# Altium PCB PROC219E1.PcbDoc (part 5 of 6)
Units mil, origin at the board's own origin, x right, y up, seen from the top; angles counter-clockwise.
Board outline 5354.33 x 5354.33 mil, 4 copper layers (Top Layer, Inner Layer 1, Inner Layer 2, Bottom Layer), stack 62.449 mil thick; 579 components, 299 nets, 1709 pads, 802 vias.
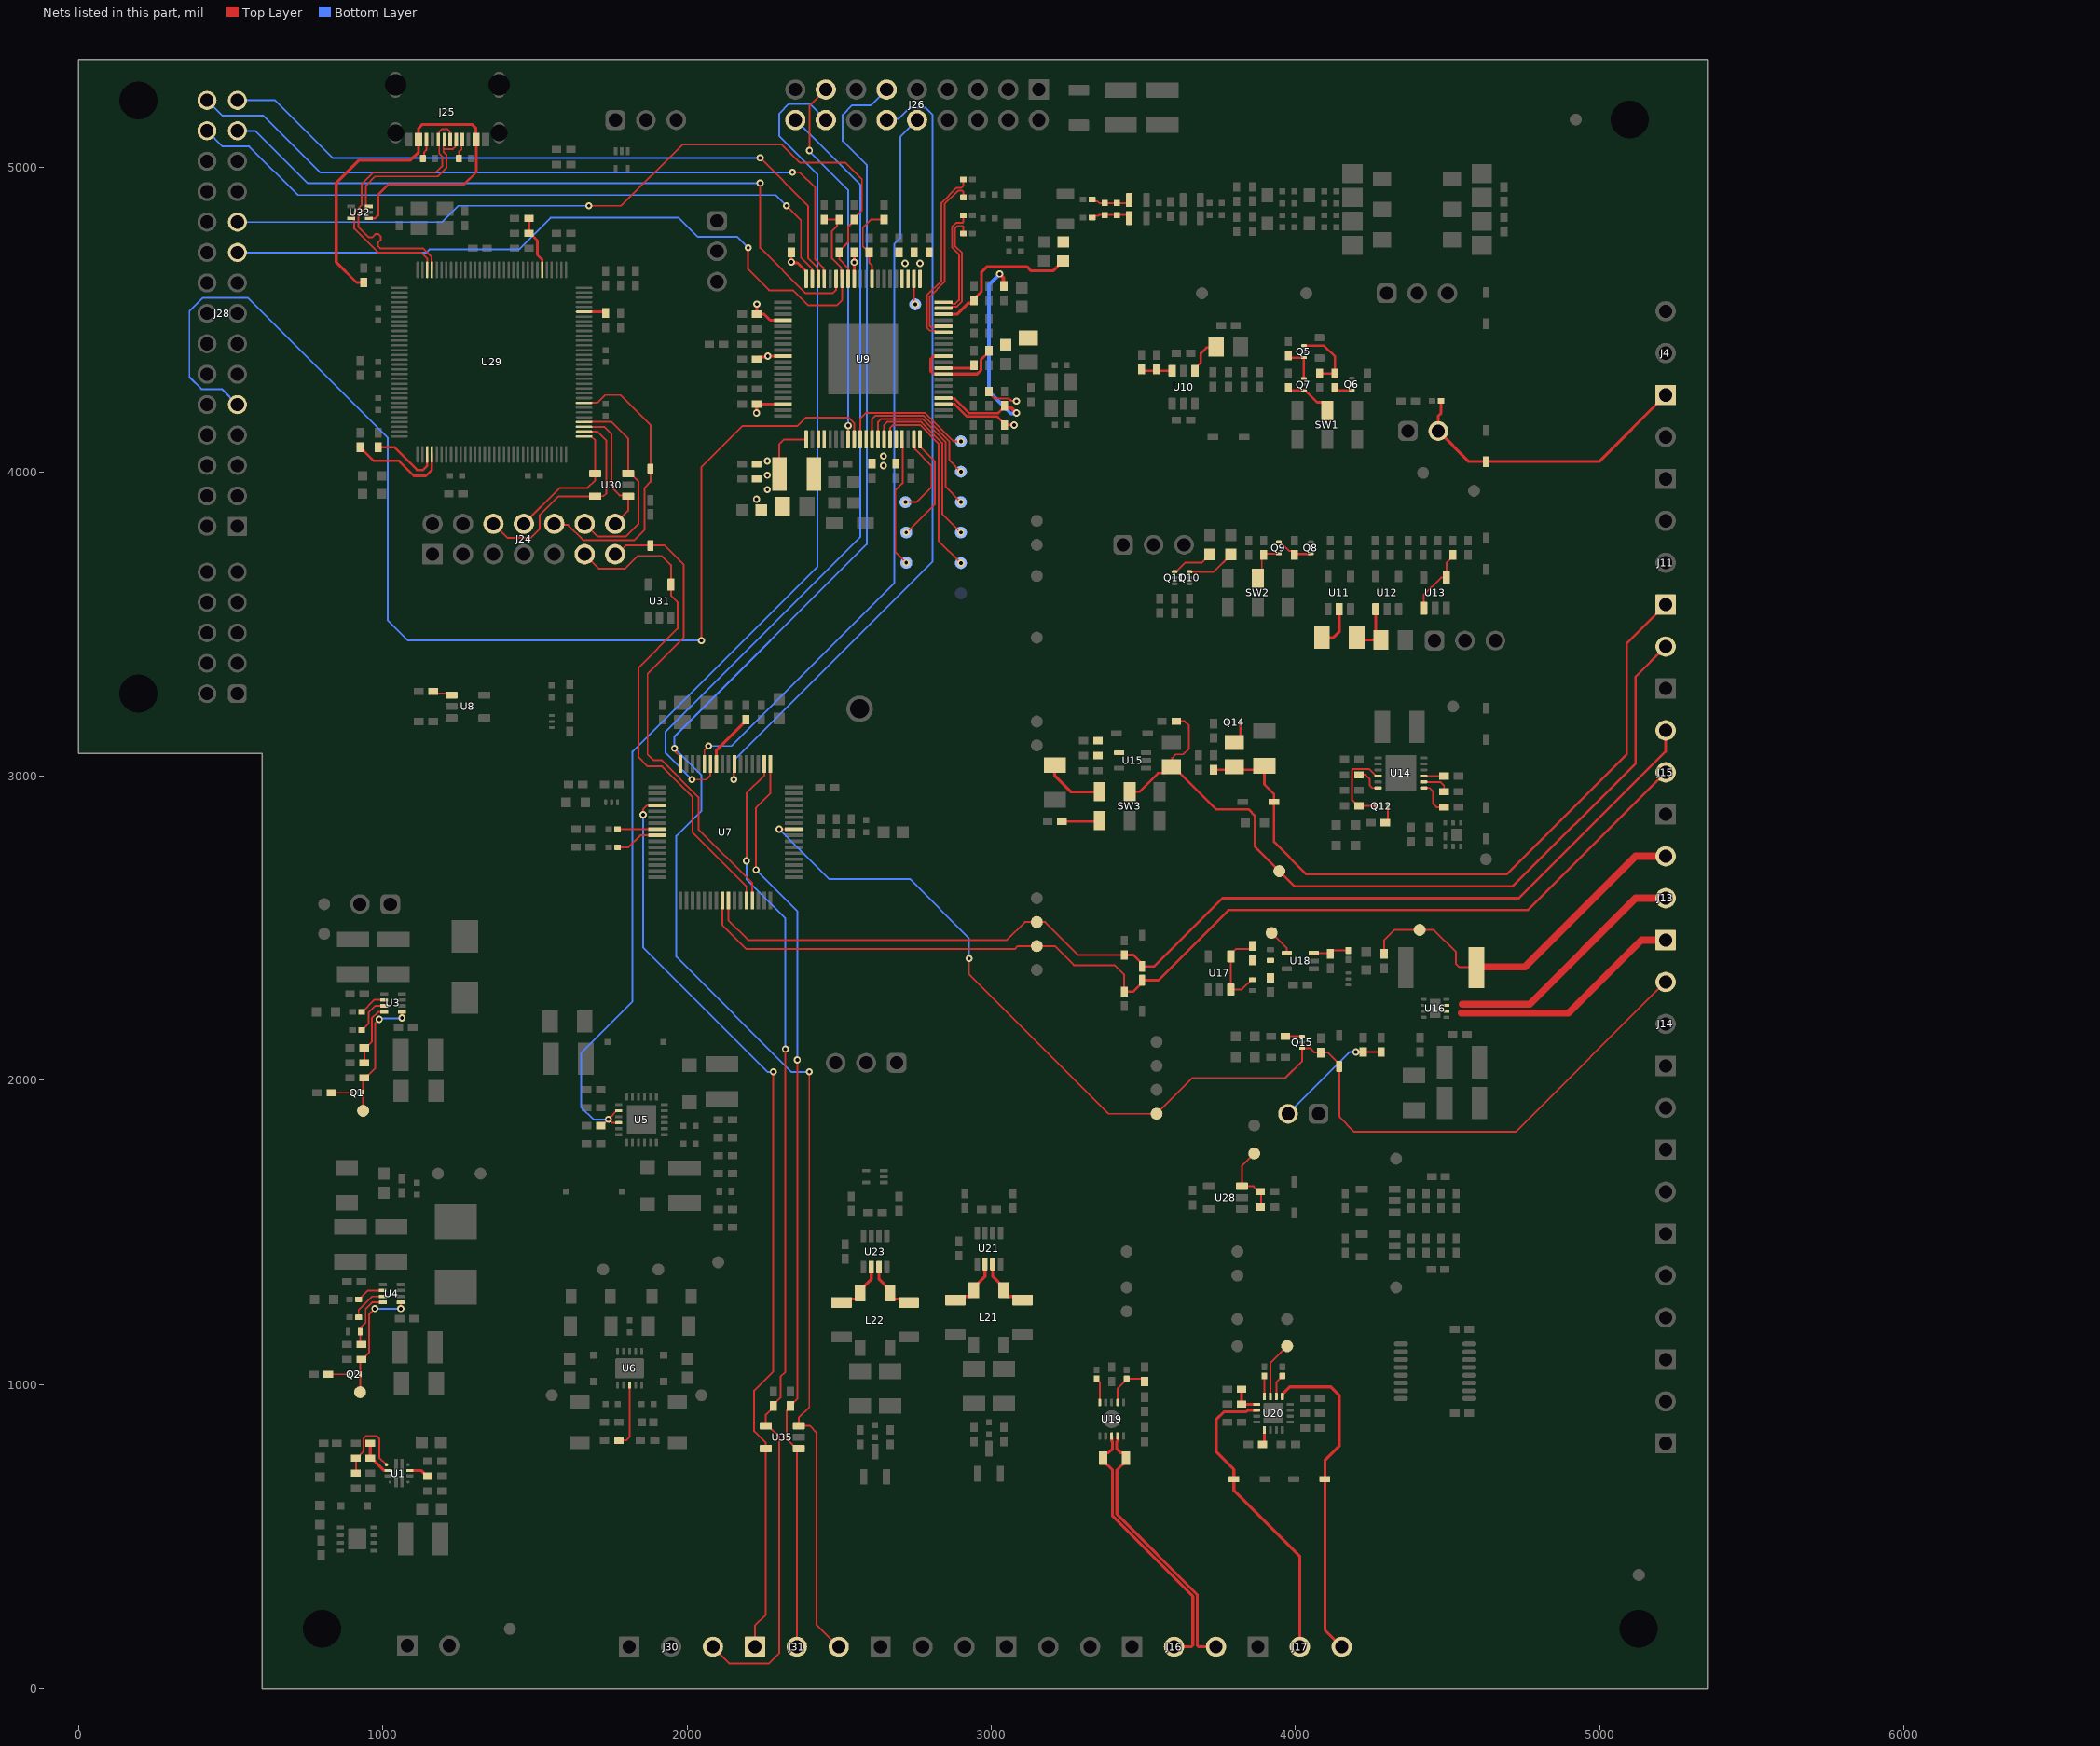
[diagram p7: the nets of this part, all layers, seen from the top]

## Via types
v1: diameter 23.62, hole 11.81, Top Layer to Bottom Layer, tented both sides, 802 vias

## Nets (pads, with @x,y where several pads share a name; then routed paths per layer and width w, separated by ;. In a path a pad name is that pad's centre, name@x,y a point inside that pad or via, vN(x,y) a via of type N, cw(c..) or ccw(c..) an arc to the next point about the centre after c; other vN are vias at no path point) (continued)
NetJ12_2: J12.2 R111.2 R112.1 | length 390.4
  Top Layer w5.91: v1(4198.27,2092.9) 4222.06,2092.9 R112.1@4222.44,2092.52 R111.2@4281.5,2092.52
  Bottom Layer w5.91: J12.2@3975.59,1889.76 4179,2093.17 4197.99,2093.17 v1(4198.27,2092.9)
NetL13_1: L13.1 U9.23 U9.24
NetL21_1: L21.1 R133.1 U21.7 | length 177.8
  Top Layer w9.84: U21.7@3004.92,1395.67 3004.92,1355.32 3041.34,1318.9 L21.1@3041.34,1310.04 3041.34,1302.17 3054.13,1289.37 3088.58,1289.37 R133.1@3100.39,1277.56
NetL21_2: L21.2 R138.1 U21.6 | length 177.8
  Top Layer w9.84: R138.1@2883.86,1277.56 2895.67,1289.37 2930.12,1289.37 2942.91,1302.17 L21.2@2942.91,1310.04 2942.91,1318.9 2979.33,1355.32 U21.6@2979.33,1395.67
NetL22_1: L22.1 R139.1 U23.7 | length 179
  Top Layer w9.84: U23.7@2630.91,1385.83 2630.91,1345.47 2667.32,1309.05 L22.1@2667.32,1300.2 2667.32,1292.32 2679.13,1280.51 2717.52,1280.51 R139.1@2728.35,1269.68
NetL22_2: L22.2 R144.1 U23.6 | length 178.4
  Top Layer w9.84: R144.1@2507.87,1269.68 2518.7,1280.51 2556.1,1280.51 2568.9,1293.31 L22.2@2568.9,1300.2 2568.9,1309.05 2605.31,1345.47 U23.6@2605.31,1385.83
NetQ1_1: Q1.1@935.04,1958.66 R9.1 TP2.1 U3.1 | length 423.8
  Top Layer w5.91: TP2.1@935.04,1899.61 Q1.1@935.04,1958.66 935.04,2003.94 R9.1@938.98,2007.87 947.83,2016.73 952.43,2016.73 974.41,2038.71 974.41,2186.62 v1(987.97,2200.18) ; U3.1@1062.6,2224.41 1062.99,2224.02 v1(1062.99,2204.72)
  Bottom Layer w5.91: v1(987.97,2200.18) 992.52,2204.72 994.79,2202.45 1060.72,2202.45 v1(1062.99,2204.72)
NetQ1_3: Q1.3@895.67,1958.66 R13.2 | length 65
  Top Layer w5.91: R13.2@830.71,1958.66 Q1.3@895.67,1958.66
NetQ2_1: Q2.1@925.2,1033.46 R15.1 TP4.1 U4.1 | length 402.9
  Top Layer w5.91: TP4.1@925.2,974.41 925.2,999.61 925.28,999.69 925.28,1016.06 925.2,1016.14 Q2.1@925.2,1033.46 925.2,1078.74 937.99,1091.54 942.06,1091.54 954.72,1104.2 954.72,1230.32 v1(973.5,1249.09) ; v1(1058.66,1249.09) U4.1@1058.66,1269.68
  Bottom Layer w5.91: v1(973.5,1249.09) v1(1058.66,1249.09)
NetQ2_3: Q2.3@885.83,1033.46 R19.2 | length 65
  Top Layer w5.91: R19.2@820.87,1033.46 Q2.3@885.83,1033.46
NetQ5_1: Q5.1@4027.56,4375 Q7.3@4027.56,4306.1 R70.2 | length 122.9
  Top Layer w7.87: R70.2@3976.38,4381.89 3983.27,4375 Q5.1@4027.56,4375 Q7.3@4027.56,4306.1
NetQ5_3: Q5.3@4027.56,4414.37 R68.2 R69.2 | length 223.7
  Top Layer w7.87: Q5.3@4027.56,4414.37 4093.5,4414.37 4129.92,4377.95 R69.2@4129.92,4322.83 R68.2@4078.74,4322.83
NetQ6_3: Q6.3@4185.04,4267.72 R69.1 | length 58.4
  Top Layer w7.87: R69.1@4129.92,4275.59 4137.8,4267.72 Q6.3@4185.04,4267.72
NetQ7_1: Q7.1@4027.56,4266.73 R72.1 SW1.6 | length 170.6
  Top Layer w7.87: R72.1@3972.44,4277.56 R72.1@3975.39,4274.61 ; R72.1@3976.38,4275.59 3976.38,4274.61 3984.25,4266.73 Q7.1@4027.56,4266.73 4032.28,4266.73 4070.67,4228.35 4088.58,4228.35 4104.33,4212.6 SW1.6@4104.33,4200.79
NetQ8_1: Q8.1@4050.42,3730.31 Q9.3@3944.88,3769.69 R82.2 | length 126.6
  Top Layer w5.91: Q9.3@3940.16,3769.69 Q9.3@3944.88,3769.69 3949.61,3769.69 3980.12,3739.17 3991.14,3739.17 R82.2@4000,3730.31
  Top Layer w7.87: R82.2@4000,3730.31 Q8.1@4050.42,3730.31
NetQ9_1: Q9.1@3944.88,3730.31 R87.1 SW2.6 | length 135.8
  Top Layer w5.91: SW2.6@3875.98,3649.61 3889.16,3662.78 3889.16,3719.87 3899.61,3730.31 Q9.1@3944.88,3730.31
NetQ10_3: Q10.3@3651.57,3671.26 R81.1 | length 160
  Top Layer w5.91: Q10.3@3651.57,3671.26 3731.3,3671.26 3787.4,3727.36 R81.1@3787.4,3728.35
NetQ11_3: Q11.3@3602.36,3671.26 R80.1 | length 140.4
  Top Layer w5.91: Q11.3@3602.36,3671.26 3607.09,3671.26 3636.61,3700.79 3690.94,3700.79 3701.77,3711.61 3702.76,3711.61 3718.5,3727.36 R80.1@3718.5,3728.35
NetQ12_1: Q12.1@4263.78,2901.57 R91.2 U14.10 | length 280.7
  Top Layer w5.91: Q12.1@4263.78,2901.57 R91.2@4208.66,2901.57 4204.72,2901.57 4185.96,2920.34 4185.96,3018.63 4190.03,3022.7 4242.06,3022.7 4264.76,3000 U14.10@4271.65,3000
NetQ12_3: Q12.3@4303.15,2901.57 R94.2 | length 58.4
  Top Layer w5.91: R94.2@4295.28,2846.46 4303.15,2854.33 Q12.3@4303.15,2901.57
NetQ14_3: Q14.3@3818.9,3176.68 R98.1 | length 74.8
  Top Layer w7.87: R98.1@3799.21,3110.06 3818.9,3129.75 Q14.3@3818.9,3176.68
NetQ15_3: Q15.3@4021.85,2144.47 R109.2 | length 55.1
  Top Layer w5.91: R109.2@3966.73,2144.47 Q15.3@4021.85,2144.47
NetR2_1: R2.1 R4.2 U1.1 | length 281.2
  Top Layer w5.91: R2.1@911.42,708.66 R4.2@911.42,757.87 915.35,757.87 935.96,778.48 935.96,821.78 944.89,830.71 980.32,830.71 988.19,822.83 988.19,759.84 U1.1@1011.81,736.22
NetR4_1: R4.1 R6.2 U1.2 | length 125
  Top Layer w9.84: R6.2@958.66,807.09 R4.1@958.66,757.87 965.55,750.98 969.9,750.98 1003.36,717.52 U1.2@1017.72,717.52
NetR5_2: R5.2 U1.9 | length 66.8
  Top Layer w9.84: U1.9@1088.58,717.52 1125,717.52 1143.7,698.82 R5.2@1147.64,698.82
NetR8_1: R8.1 U3.6 | length 90.5
  Top Layer w5.91: R8.1@930.17,2224.41 931.88,2224.41 971.25,2263.78 U3.6@1004.33,2263.78
NetR10_1: R10.1 R12.2 U3.8 | length 208.5
  Top Layer w5.91: R12.2@938.98,2057.09 R10.1@938.98,2106.3 942.91,2106.3 951.77,2115.16 964.5,2127.89 964.5,2204.66 984.25,2224.41 U3.8@1004.33,2224.41
NetR11_1: R11.1 U3.7 | length 128
  Top Layer w5.91: R11.1@930.17,2165.35 931.88,2165.35 938.23,2171.7 938.23,2171.84 953.53,2187.14 953.53,2223.22 974.41,2244.09 U3.7@1004.33,2244.09
NetR14_1: R14.1 U4.6 | length 89.3
  Top Layer w5.91: R14.1@925.2,1279.53 925.2,1282.68 951.57,1309.06 U4.6@1000.39,1309.06
NetR16_1: R16.1 R18.2 U4.8 | length 191.3
  Top Layer w5.91: R18.2@929.13,1131.89 925.51,1135.51 925.51,1181.1 925.51,1185.6 943.33,1203.42 943.33,1248.45 964.57,1269.68 U4.8@1000.39,1269.68
NetR17_1: R17.1 U4.7 | length 123.1
  Top Layer w5.91: R17.1@920.32,1220.47 920.32,1245.13 964.57,1289.37 U4.7@1000.39,1289.37
NetR29_2: R29.2 U6.8 | length 210.8
  Top Layer w5.91: R29.2@1775.59,816.93 1801.18,816.93 1811.02,826.77 U6.8@1811.02,998.03
NetR30_2: R30.2 U7.42 | length 185.6
  Top Layer w9.84: U7.42@2096.46,3039.37 2096.46,3084.65 2192.91,3181.1 R30.2@2192.91,3185.04
NetR33_1: R33.1 U7.56 | length 129.9
  Top Layer w5.91: R33.1@1771.65,2824.8 U7.56@1901.57,2824.8
NetR34_1: R34.1 U7.57 | length 146.2
  Top Layer w5.91: R34.1@1771.65,2765.75 1806.98,2765.75 1846.36,2805.12 U7.57@1901.57,2805.12
NetR39_2: R39.2 U8.1 | length 64.9
  Top Layer w5.91: R39.2@1165.35,3277.56 1171.19,3271.72 1219.42,3271.72 U8.1@1225.39,3265.75
NetR59_2: R59.2 U9.49 | length 106.2
  Top Layer w9.84: U9.49@2842.52,4340.55 2936.02,4340.55 2942.91,4347.44 R59.2@2942.91,4350.39
NetR60_1: R60.1 R62.2 U10.3 | length 102.4
  Top Layer w7.87: R60.1@3494.09,4336.61 3499.02,4331.69 U10.3@3594.49,4331.69
NetR61_1: R61.1 U10.1 | length 124.9
  Top Layer w7.87: U10.1@3669.29,4331.69 3669.29,4339.57 3688.98,4359.25 3688.98,4389.76 3707.33,4408.12 3738.2,4408.12 R61.1@3739.53,4409.45
NetR73_1: R73.1 U11.2 | length 139.1
  Top Layer w9.84: R73.1@4087.06,3454.28 4124.02,3454.28 4143.7,3473.96 U11.2@4143.7,3548.23
NetR73_2: R73.2 R74.1 U12.1 | length 186.2
  Top Layer w9.84: R73.2@4200.79,3454.72 4208.43,3447.09 R74.1@4275.59,3447.09 ; U12.1@4263.78,3548.23 4263.78,3464.17 R74.1@4280.87,3447.09
NetR78_2: R78.2 U13.1 U13.4 | length 224.4
  Top Layer w5.91: U13.1@4421.26,3551.18 4421.26,3594.49 4478.85,3652.08 4494.6,3652.08 U13.4@4496.06,3653.54 4496.06,3700.79 4517.72,3722.44 R78.2@4517.72,3726.38
NetR88_2: R88.2 U14.12 | length 94.5
  Top Layer w5.91: R88.2@4208.66,3003.94 4229.93,3003.94 4244.02,2989.85 4244.02,2968.57 4251.97,2960.63 U14.12@4271.65,2960.63 ; U14.12@4271.65,2961.07 U14.12@4272.8,2961.07
NetR89_2: R89.2 U14.3 | length 66.9
  Top Layer w5.91: U14.3@4421.26,3000 R89.2@4488.19,3000
NetR92_2: R92.2 U14.1 | length 116.7
  Top Layer w5.91: U14.1@4421.26,2960.63 4440.94,2960.63 4452.76,2948.82 4452.76,2908.4 4463.52,2897.64 R92.2@4488.19,2897.64
NetR93_2: R93.2 U14.2 | length 91.5
  Top Layer w5.91: U14.2@4421.26,2980.31 4476.38,2980.31 4488.19,2968.5 R93.2@4488.19,2948.82
NetR104_2: R104.2 SW3.5 | length 204.6
  Top Layer w9.84: R104.2@3208.66,3035.43 3208.66,3000 3260.65,2948.02 SW3.5@3356.3,2948.02
NetR107_1: R107.1 SW3.1 | length 125.3
  Top Layer w7.87: R107.1@3232.28,2850.39 3353.17,2850.39 SW3.1@3356.3,2853.53
NetR113_1: R113.1 R114.1 U17.3 U17.4 | length 283
  Top Layer w5.91: R113.1@3858.27,2336.61 3858.27,2332.68 3823.82,2298.23 U17.3@3787.4,2298.23 U17.4@3787.4,2406.5 3787.4,2414.37 3804.13,2431.1 R114.1@3858.27,2431.1
NetR118_1: R118.1 R119.1 U18.3 | length 117.7
  Top Layer w5.91: U18.3@4060.04,2417.32 4112.2,2417.32 R119.1@4114.17,2415.35 ; R119.1@4114.17,2417.37 4123.03,2426.23 R118.1@4173.23,2426.23
NetR123_1: R123.1 R126.1 U19.2 | length 152.6
  Top Layer w5.91: U19.2@3415.35,940.94 3415.35,987.41 3444.88,1016.94 R126.1@3444.88,1018.65 3495.13,1018.65 R123.1@3503.94,1009.84
NetR125_1: R125.1 U19.5 | length 81.8
  Top Layer w5.91: R125.1@3346.46,1018.65 3346.46,1016.94 3356.3,1007.09 U19.5@3356.3,940.94
NetR128_1: R128.1 U20.8 | length 67.9
  Top Layer w5.91: U20.8@3897.64,960.63 R128.1@3897.64,1028.49
NetR129_1: R129.1 U20.13 | length 49.7
  Top Layer w9.84: R129.1@3891.73,803.15 3897.64,809.05 U20.13@3897.64,850.39
NetR130_2: R130.2 R132.1 U20.9 | length 98.4
  Top Layer w9.84: R132.1@3822.83,984.25 R130.2@3822.83,935.04 U20.9@3872.05,935.04
NetR131_1: R131.1 U20.6 | length 76
  Top Layer w5.91: U20.6@3937.01,960.63 3937.01,1007.09 3956.69,1026.78 R131.1@3956.69,1028.49
NetR152_1: R152.1 R153.2 TP57.1 U28.3 | length 252.3
  Top Layer w5.91: TP57.1@3864.31,1759.24 3823.82,1718.74 U28.3@3823.82,1651.57 3862.2,1651.57 3879.92,1633.86 R152.1@3883.86,1633.86 3887.3,1630.42 R153.2@3887.3,1574.8
NetR159_2: R159.2 U29.3 | length 235.5
  Top Layer w7.87: R159.2@984.25,4080.71 1037.4,4080.71 1112.2,4005.91 1131.89,4005.91 1145.67,4019.69 U29.3@1145.67,4057.09
NetR160_2: R160.2 U29.4 | length 337
  Top Layer w7.87: R160.2@925.2,4080.71 925.2,4076.77 933.07,4068.9 937.01,4068.9 970.47,4035.43 1053.15,4035.43 1102.36,3986.22 1141.73,3986.22 1161.42,4005.91 U29.4@1161.42,4057.09
NetR161_1: R161.1 R162.2 U29.70 | length 189.5
  Top Layer w7.87: R161.1@1480.31,4832.68 R162.2@1480.32,4783.46 1484.25,4783.46 1507.87,4759.84 1507.87,4712.78 1523.62,4697.04 U29.70@1523.62,4663.39
NetR163_2: R163.2 U29.59 | length 72.5
  Top Layer w7.87: U29.59@1661.42,4525.59 1728.35,4525.59 R163.2@1732.28,4521.65
NetTP9_1: TP9.1 U9.40 | length 366.3
  Top Layer w5.91: v1(2720.47,3800) 2721.26,3800 2814.96,3893.7 2814.96,4033.46 2765.75,4082.68 U9.40@2765.75,4106.3
NetTP10_1: TP10.1 U9.37 | length 430.5
  Top Layer w5.91: U9.37@2706.69,4106.3 2708.37,4104.62 2708.37,3962.31 2685.04,3938.98 2685.04,3736.22 v1(2720.47,3700.79)
NetTP11_1: TP11.1 U9.39 | length 286.8
  Top Layer w5.91: v1(2717.67,3900) 2754.33,3900 2803.15,3948.82 2803.15,4019.69 2749.02,4073.82 2749.02,4103.35 U9.39@2746.06,4106.3
NetTP12_1: TP12.1 U9.62 | length 85.5
  Top Layer w5.91: U9.62@2746.06,4633.86 2746.06,4553.94 v1(2750,4550)
NetTP13_1: TP13.1 U9.33 | length 532.7
  Top Layer w5.91: U9.33@2627.95,4106.3 2627.95,4163.39 2637.92,4173.35 2773.77,4173.35 2850.39,4096.73 2850.39,3949.61 v1(2900,3900)
NetTP14_1: TP14.1 U9.34 | length 590.8
  Top Layer w5.91: U9.34@2647.64,4106.3 2647.64,4153.54 2657.54,4163.45 2769.67,4163.45 2838.58,4094.53 2838.58,3861.42 v1(2900,3800)
NetTP15_1: TP15.1 U9.32 | length 474.5
  Top Layer w5.91: U9.32@2608.27,4106.3 2608.27,4173.23 2618.3,4183.26 2777.87,4183.26 2862.2,4098.93 2862.2,4037.8 v1(2900,4000)
NetTP16_1: TP16.1 U9.35 | length 649.5
  Top Layer w5.91: U9.35@2667.32,4106.3 2667.32,4143.7 2677.17,4153.54 2765.57,4153.54 2826.77,4092.34 2826.77,3773.26 v1(2900.02,3700.02)
  Bottom Layer w5.91: v1(2900.02,3700.02) TP16.1@2900.54,3700.02
NetTP17_1: TP17.1 U9.30 | length 444.9
  Top Layer w5.91: U9.30@2568.9,4106.3 2568.9,4173.23 2588.83,4193.17 2781.98,4193.17 2875.14,4100 v1(2900,4100)
NetTP47_1: TP47.1 U20.7 | length 188.2
  Top Layer w5.91: U20.7@3917.32,960.63 3917.32,1070.87 TP47.1@3972.44,1125.98
P_TEMP1: D30.1 J15.3 R122.1 TP40.1 U7.9 | length 3623.6
  Top Layer w5.91: U7.9@2135.83,2590.55 2135.83,2525.59 2200.79,2460.63 3051.18,2460.63 3110.24,2519.68 3177.17,2519.68 3285.43,2411.42 R122.1@3437.01,2411.42
  Top Layer w7.87: R122.1@3437.01,2411.42 3466.54,2411.42 3496.06,2381.89 D30.1@3496.06,2374.02 3535.43,2374.02 3759.84,2598.43 4734.25,2598.43 5216.54,3080.71 J15.3@5216.54,3149.61
P_TEMP2: D29.1 J15.2 R121.1 TP39.1 U7.8 | length 3615.1
  Top Layer w5.91: U7.8@2116.14,2590.55 2116.57,2590.12 2116.57,2509.41 2194.88,2431.1 3076.77,2431.1 3086.61,2440.94 3208.66,2440.94 3271.65,2377.95 3405.51,2377.95 3437.01,2346.46 R121.1@3437.01,2291.34
  Top Layer w7.87: R121.1@3437.01,2291.34 3466.54,2291.34 3496.06,2320.87 D29.1@3496.06,2328.74 3549.21,2328.74 3779.53,2559.06 4763.78,2559.06 J15.2@5216.54,3011.81
PA19_SWDIO: J24.11 U7.12 U31.4 | length 1672.6
  Top Layer w5.91: J24.11@1663.39,3728.74 1711.02,3681.1 1795.69,3681.1 1838.07,3723.49 1916.44,3723.49 1946.85,3693.08 U31.4@1946.85,3628.94 1946.85,3593.63 1968.5,3571.98 1968.5,3484.25 1840.55,3356.3 1840.55,3061.02 1870.08,3031.5 1917.78,3031.5 2017.72,2931.56 2017.72,2814.96 2194.88,2637.8 U7.12@2194.88,2590.55
PA20_SWCLK: D37.1 J24.13 U7.13 | length 1575.5
  Top Layer w5.91: J24.13@1763.39,3728.74 1769.15,3728.74 1798.28,3757.87 D37.1@1879.92,3757.87 1926.39,3757.87 1988.19,3696.07 1988.19,3454.55 1870.08,3336.44 1870.08,3070.87 1889.76,3051.18 1916.95,3051.18 2037.4,2930.73 2037.4,2824.8 2214.57,2647.64 U7.13@2214.57,2590.55
PD_VREF: R102.1 R106.2 U15.4
PL_FB: D26.1 J14.3 Q15.1@4021.85,2105.1 R108.1 TP30.1 U7.25 | length 3949.8
  Top Layer w5.91: v1(2303.15,2824.8) U7.25@2350.39,2824.8 ; v1(2927.17,2400.13) 2927.17,2348.43 3385.83,1889.76 TP30.1@3543.31,1889.76 3661.42,2007.87 3966.54,2007.87 4021.85,2063.19 Q15.1@4021.85,2105.1 4048.45,2105.1 4062.99,2090.55 R108.1@4082.68,2090.55 4106.3,2090.55 4143.7,2053.15 D26.1@4143.7,2045.28 4143.7,1879.92 4192.91,1830.71 4724.41,1830.71 J14.3@5216.54,2322.83
  Bottom Layer w5.91: v1(2303.15,2824.8) 2466.54,2661.42 2732.28,2661.42 2927.17,2466.54 v1(2927.17,2400.13)
PL_OUT1: J13.1 U16.2 | length 770.9
  Top Layer w23.62: 4545.15,2220.47 4897.64,2220.47 5137.8,2460.63 J13.1@5216.54,2460.63
PL_OUT2: J13.2 U16.3 | length 813.2
  Top Layer w23.62: 4547.65,2250.02 4769.7,2250.02 5118.11,2598.43 J13.2@5216.54,2598.43
PL_SNS_CdM: J13.3 R116.1 R117.2 TP36.1 | length 1208.7
  Top Layer w5.91: R117.2@4291.34,2415.35 4291.34,2460.63 4324.66,2493.95 TP36.1@4408.09,2493.95 4454.87,2493.95 4527.56,2421.26 4527.56,2381.89 4537.4,2372.05 R116.1@4596.46,2372.05
  Top Layer w23.62: R116.1@4596.46,2372.05 4753.94,2372.05 5118.11,2736.22 J13.3@5216.54,2736.22
PLC_IRQ: J28.21 R44.1 R49.2 U9.73 | length 2575.6
  Top Layer w5.91: v1(1677.17,4874.02) 1783.46,4874.02 1984.25,5074.8 2311.02,5074.8 2370.08,5015.75 2519.69,5015.75 2574.8,4960.63 2574.8,4858.27 2549.21,4832.68 R44.1@2549.21,4828.74 2549.21,4824.8 2529.61,4805.2 2529.61,4754.02 2500,4724.41 2500,4698.82 2529.53,4669.29 U9.73@2529.53,4633.86
  Bottom Layer w5.91: J28.21@521.85,4820.47 1194.49,4820.47 1248.03,4874.02 v1(1677.17,4874.02)
PLC_N: C101.2 C102.2 L15.1 R54.1 | length 132
  Top Layer w5.91: R54.1@3331.28,4894.56 3337.62,4888.21 3349.38,4888.21 3354.65,4882.94 C101.2@3373.35,4882.94 C102.2@3412.72,4882.94 3445.2,4882.94 3453.47,4891.21 L15.1@3453.47,4892.78
PLC_nRST: J28.9 U9.29 | length 4131
  Top Layer w5.91: v1(2047.24,3444.88) 2047.24,4015.75 2181.1,4149.61 2362.2,4149.61 2389.76,4177.17 2531.5,4177.17 2549.21,4159.45 U9.29@2549.21,4106.3
  Bottom Layer w5.91: J28.9@521.85,4220.47 470.67,4271.65 403.54,4271.65 364.17,4311.02 364.17,4527.56 407.48,4570.87 557.09,4570.87 1015.86,4112.09 1015.86,3511.69 1082.68,3444.88 v1(2047.24,3444.88)
PLC_P: C101.1 C102.1 L19.1 R52.1 | length 130.5
  Top Layer w5.91: R52.1@3331.28,4835.5 3336.74,4840.96 3351.15,4840.96 3353.76,4843.57 C101.1@3373.35,4843.57 C102.1@3412.72,4843.57 3445.2,4843.57 3453.47,4835.31 L19.1@3453.47,4833.73
PLC_SPI1_CLK: J28.27 U9.75 | length 2354.2
  Top Layer w5.91: v1(2240.16,4948.82) 2240.16,4735.75 2389.3,4586.61 2477.74,4586.61 2490.07,4598.94 2490.07,4633.77 U9.75@2490.16,4633.86
  Bottom Layer w5.91: J28.27@521.85,5120.47 580.32,5120.47 751.97,4948.82 v1(2240.16,4948.82)
PLC_SPI1_CS0: J28.30 U9.77 | length 2429.8
  Top Layer w5.91: v1(2346.46,4984.25) 2370.08,4984.25 2421.26,4933.07 2421.26,4697.44 2447.83,4670.87 2447.83,4636.81 U9.77@2450.79,4633.86
  Bottom Layer w5.91: J28.30@421.85,5220.47 471.37,5170.95 606.6,5170.95 793.48,4984.08 v1@2346.28,4984.08
PLC_SPI1_D0: J28.28 U9.79 | length 2282.2
  Top Layer w5.91: v1(2326.77,4874.02) 2374.02,4826.77 2374.02,4703.9 2410.24,4667.68 2410.24,4635.04 U9.79@2411.42,4633.86
  Bottom Layer w5.91: J28.28@421.85,5120.47 473.43,5068.9 561.02,5068.9 720.78,4909.15 2291.64,4909.15 v1(2326.77,4874.02)
PLC_SPI1_D1: J28.29 U9.78 | length 2273.3
  Top Layer w5.91: v1(2240.16,5031.5) 2397.64,4874.02 2397.64,4701.98 2429.01,4670.61 2429.01,4635.95 U9.78@2431.1,4633.86
  Bottom Layer w5.91: J28.29@521.85,5220.47 645.67,5220.47 834.65,5031.5 v1(2240.16,5031.5)
PLC_SPI1_IRQ: J28.19 R42.1 R47.2 U9.74 | length 2540.3
  Top Layer w5.91: v1(2200.79,4736.22) 2200.79,4665.35 2269.62,4596.52 2348.67,4596.52 2398.5,4546.69 2491.57,4546.69 2509.84,4564.96 U9.74@2509.84,4633.86 2506.89,4636.81 2506.89,4670.28 2476.38,4700.79 2476.38,4790.9 2493.07,4807.59 2493.07,4821.81 2498.04,4826.78 2496.08,4828.74 R42.1@2450.79,4828.74 R42.1@2450.79,4832.68
  Bottom Layer w5.91: J28.19@521.85,4720.47 1143.22,4720.47 1152.97,4730.22 1446.75,4730.22 1551.18,4834.65 1972.44,4834.65 2035.43,4771.65 2165.35,4771.65 v1(2200.79,4736.22)
PLC_ZC_IN: J26.15 U9.28 | length 1225
  Top Layer w5.91: v1(2401.99,5055.84) 2401.99,5201.99 J26.15@2455.91,5255.91 ; v1(2529.33,4151.38) 2529.43,4151.28 2529.43,4106.4 U9.28@2529.53,4106.3
  Bottom Layer w5.91: v1(2401.99,5055.84) 2401.99,5053.46 2529.53,4925.93 2529.53,4919.68 2529.45,4919.6 2529.45,4903.23 2529.53,4903.15 2529.53,4786.26 2529.33,4786.07 v1(2529.33,4151.38)
PLL_AVDD_1V2: C59.2 L12.2 U9.44 | length 850
  Top Layer w7.87: U9.44@2842.52,4242.13 2843.12,4241.53 2877.17,4241.53 2925.85,4192.85 3023.56,4192.85 3043.31,4212.6 C59.2@3043.31,4216.54
  Top Layer w11.81: v1@3027.38,4649 3039.6,4636.78 3039.6,4611.97 L12.2@3041.34,4610.24 ; C59.2@3043.31,4216.54 3043.31,4215.82 3049.21,4209.91 3065.68,4209.91 v1(3082.68,4192.91)
  Bottom Layer w11.81: v1(3027.38,4650.01) 2991.76,4614.39 2991.76,4263.67 3063.53,4191.9 3080.16,4191.9 v1@3082.54,4189.52
PP: D16.1 J4.1 J6.2 R67.1 | length 981.5
  Top Layer w9.84: R67.1@4478.35,4232.28 4478.35,4192.91 4469.29,4183.86 J6.2@4469.29,4133.86 4569.68,4033.46 D16.1@4625.98,4033.46 4998.03,4033.46 J4.1@5216.54,4251.97
Proximity_Detection: J10.2 R103.1 R105.2 SW3.6 TP29.1 | length 2732.2
  Top Layer w5.91: R105.2@3592.52,3030.06 3594.49,3032.03 3594.49,3059.06 3606.3,3070.87 3630.42,3070.87 3649.61,3090.06 3649.61,3165.35 3635.04,3179.92 R103.1@3608.14,3179.92
  Top Layer w7.87: SW3.6@3454.72,2948.02 3487.22,2948.02 3548.21,3009 3571.46,3009 R105.2@3592.52,3030.06 3599.02,3030.06 3739.32,2889.76 3846.46,2889.76 3866.14,2870.08 3866.14,2767.72 TP29.1@3946.85,2687.01 3996.06,2637.8 4714.57,2637.8 5118.11,3041.34 5118.11,3326.77 J10.2@5216.54,3425.2
PW_EN_EXT: J26.16 R27.1 U5.8 U5.10 | length 4053.2
  Top Layer w5.91: R27.1@1716.38,1850.59 1720.32,1850.59 v1(1740.99,1871.25) v1@1742.48,1871.25 ; U5.10@1775.44,1860.43 1753.31,1860.43 v1@1742.48,1871.25 ; U5.8@1775.44,1899.8 1768.55,1899.8 1743.94,1875.19 1743.94,1871.25 v1@1742.48,1871.25
  Bottom Layer w5.91: v1(1740.99,1871.25) 1691.74,1871.25 1651.31,1911.68 1651.31,2088.81 1820.87,2258.37 1820.87,3080.71 2429.13,3688.98 2429.13,4976.38 2303.15,5102.36 2303.15,5177.17 2334.79,5208.81 2403,5208.81 J26.16@2455.91,5155.91
R_MIRROR_OUT: J26.12 U7.39 | length 2685.2
  Top Layer w5.91: v1(2153.54,2988.19) 2154.53,2989.17 2154.53,3038.39 U7.39@2155.51,3039.37
  Bottom Layer w5.91: v1(2153.54,2988.19) 2153.54,3051.18 2807.09,3704.72 2807.09,5173.23 2783.99,5196.32 2731.76,5196.32 2694.77,5159.34 2659.34,5159.34 J26.12@2655.91,5155.91
RCD_FAULT_SCL: J30.3 R168.1 U7.34 U35.4 | length 3299.9
  Top Layer w5.91: J30.3@2085.04,137.8 2140.16,82.68 2267.72,82.68 2303.15,118.11 2303.15,827.76 2266.73,864.17 U35.4@2258.86,864.17 2258.86,900.59 R168.1@2283.46,925.2 ; v1(2195.2,2720.94) 2195.2,2943.23 2253.94,3001.97 U7.34@2253.94,3039.37 ; R168.1@2283.46,929.13 2283.46,933.07 2307.09,956.69 2307.09,1025.57 2323.25,1041.73 v1(2323.25,2102.33)
  Bottom Layer w5.91: v1(2195.2,2720.94) 2195.2,2659.97 2323.25,2531.92 v1(2323.25,2102.33)
RCD_nFAULT: J26.11 J31.3 U7.48 U35.3 | length 5943.6
  Top Layer w5.91: v1(1958.66,3090.55) 1962.05,3087.16 1962.05,3079.29 1978.35,3062.99 U7.48@1978.35,3039.37 ; U35.3@2373.03,863.7 2404.02,863.7 2425.28,842.44 2425.28,210.94 J31.3@2498.43,137.8 ; U35.3@2373.03,864.17 U35.3@2367.13,864.17 2367.13,890.75 2401.57,925.2 v1(2401.57,2027.56)
  Bottom Layer w5.91: v1(2401.57,2027.56) 2342.52,2027.56 1964.57,2405.51 1964.57,2803.15 2047.24,2885.83 2047.24,3001.97 v1(1958.66,3090.55) 1958.66,3129.92 2590.33,3761.59 2590.33,5008.1 2511.81,5086.61 2511.81,5173.24 2543.3,5204.72 2604.72,5204.72 J26.11@2655.91,5255.91
RCD_RESET: J31.1 U7.52 U35.5 | length 3049.9
  Top Layer w5.91: v1(1855.79,2872.65) 1855.79,2891.22 1867.34,2902.77 1900.8,2902.77 U7.52@1901.57,2903.54 ; J31.1@2222.83,137.8 2222.83,207.72 2258.86,243.74 U35.5@2258.86,789.37 2258.86,808.07 2220.47,846.46 2220.47,980.31 2283.46,1043.31 v1(2283.46,2027.56)
  Bottom Layer w5.91: v1(1855.79,2872.65) 1855.79,2435.55 2263.78,2027.56 v1(2283.46,2027.56)
RCD_TEST_SDA: J31.2 R167.1 U7.33 U35.1 | length 3012.2
  Top Layer w5.91: v1(2226.7,2691.42) 2226.7,2895.99 2273.62,2942.91 U7.33@2273.62,3039.37 ; R167.1@2339.65,925.74 2330.79,916.88 2330.23,916.88 2326.77,913.42 2326.77,821.85 2359.25,789.37 U35.1@2367.13,789.37 2360.63,782.87 J31.2@2360.63,137.8 ; R167.1@2339.65,929.68 2362.2,952.23 v1(2362.2,2066.93)
  Bottom Layer w5.91: v1(2226.7,2691.42) 2362.2,2555.91 v1(2362.2,2066.93)
Ref_14.5mV: C125.1 R114.2 R115.2 TP34.1 U18.4 | length 87.7
  Top Layer w5.91: TP34.1@3921.26,2484.25 3971.46,2434.06 U18.4@3971.46,2417.32
RELAY_CHECK: J26.10 U7.44 | length 2449.8
  Top Layer w5.91: U7.44@2057.09,3039.37 2057.09,3084.65 v1(2070.87,3098.43)
  Bottom Layer w5.91: v1(2070.87,3098.43) 2145.67,3098.43 2681.1,3633.86 2681.1,4748.03 2700.96,4767.89 2700.96,5100.96 J26.10@2755.91,5155.91
RS232_RX: D31.2 J17.3 U20.5 | length 1085
  Top Layer w9.84: U20.5@3956.69,960.63 3956.69,967.72 3981.1,992.13 4116.14,992.13 4143.7,964.57 4143.7,797.24 4096.46,750 D31.2@4096.46,688.98 4096.46,193.31 J17.3@4151.97,137.8
RS232_TX: D32.2 J17.2 U20.10 | length 1005.7
  Top Layer w9.84: U20.10@3872.05,915.35 3843.33,915.35 3838.11,910.14 3764.47,910.14 3740.16,885.83 3740.16,777.56 3797.24,720.47 D32.2@3797.24,688.98 3797.24,651.57 4014.17,434.65 J17.2@4014.17,137.8
RS485_N: J16.3 R124.1 U19.9 | length 892.6
  Top Layer w9.84: U19.9@3415.35,830.71 3415.16,830.51 3415.16,813.94 3412.41,811.2 3412.41,788.38 3425.2,775.59 3434.06,775.59 3442.91,766.73 3442.91,749.02 3412.43,718.54 3412.43,573.81 3676.61,309.64 3676.61,143.56 3682.37,137.8 J16.3@3738.58,137.8
RS485_P: J16.2 R124.2 U19.8 | length 892.6
  Top Layer w9.84: U19.8@3395.67,830.71 3395.87,830.51 3395.87,813.94 3398.57,811.24 3398.57,788.33 3385.83,775.59 3376.97,775.59 3368.11,766.73 3368.11,749.02 3398.59,718.54 3398.59,568.08 3662.76,303.91 3662.76,143.56 3657,137.8 J16.2@3600.79,137.8
RX_N: R56.2 U9.56 | length 569.9
  Top Layer w5.91: U9.56@2842.52,4478.35 2818.9,4478.35 2814.01,4473.46 2803.28,4473.46 2798.18,4478.56 2798.18,4575.51 2846.46,4623.79 2846.46,4879.69 2890.43,4923.67 2904.96,4923.67 2908.42,4920.21 R56.2@2908.42,4901.57
RX_P: R55.2 U9.55 | length 606.2
  Top Layer w5.91: U9.55@2842.52,4458.66 2818.9,4458.66 2814.01,4463.55 2799.18,4463.55 2788.27,4474.46 2788.27,4579.61 2836.55,4627.89 2836.55,4883.8 2886.33,4933.58 2902.48,4933.58 2908.42,4939.51 R55.2@2908.42,4960.63
Super_Cap_Char: J26.18 U7.43 | length 2662.3
  Top Layer w5.91: v1(2015.75,2988.19) 2062.99,2988.19 2076.77,3001.97 U7.43@2076.77,3039.37
  Bottom Layer w5.91: v1(2015.75,2988.19) 1929.13,3074.8 1929.13,3145.67 2569.98,3786.52 2569.98,4942.54 2356.62,5155.91 J26.18@2355.91,5155.91
TX_N: R53.2 U9.60 | length 373.2
  Top Layer w5.91: U9.60@2842.52,4557.09 2866.14,4557.09 2871.03,4552.2 2881.75,4552.2 2893.7,4564.14 2893.7,4714.57 2871.11,4737.15 2871.11,4804.41 2884.65,4817.94 2904.96,4817.94 2908.42,4821.4 R53.2@2908.42,4842.52
TX_P: R51.2 U9.59 | length 373.2
  Top Layer w5.91: U9.59@2842.52,4537.4 2866.14,4537.4 2871.03,4542.29 2885.86,4542.29 2903.61,4560.04 2903.61,4718.67 2881.02,4741.26 2881.02,4800.31 2888.75,4808.04 2904.96,4808.04 2908.42,4804.58 R51.2@2908.42,4783.46
UART_DISABLE: R45.1 R50.2 U9.69 | length 261.7
  Top Layer w5.91: U9.69@2608.27,4633.86 2608.27,4677.66 2598.43,4687.5 R50.2@2598.43,4720.47 2577.93,4740.97 2577.93,4802.33 2604.33,4828.74 R45.1@2647.64,4828.74
USB_CC1: J25.A5 R165.2 | length 66.6
  Top Layer w5.91: R165.2@1250,5029.53 1250,5051.08 1258.96,5060.04 1258.96,5089.47 J25.A5@1261.02,5091.54
USB_CC2: J25.B5 R166.2 | length 66.6
  Top Layer w5.91: R166.2@1131.89,5029.53 1135.93,5033.56 1135.93,5050.2 1142.91,5057.19 J25.B5@1142.91,5091.54
VCCA_3V3: C54.2 C86.1 C87.1 L11.1 R41.1 R46.1 U9.48 U9.51 U9.58 | length 852.6
  Top Layer w9.84: U9.51@2842.52,4379.92 2841.54,4378.94 2810.04,4378.94 2801.25,4370.15 2801.25,4330.5 2809.9,4321.85 2841.54,4321.85 U9.48@2842.52,4320.87 2953.56,4320.87 2966.28,4333.58 2966.28,4367.85 2992.13,4393.7 C86.1@2992.13,4397.64 ; U9.58@2842.52,4517.72 2887.8,4517.72 2923.62,4553.54 2936.02,4553.54 2942.91,4560.43 2942.91,4566.93 2967.32,4591.34 2967.32,4655.53 2985.01,4673.23 3118.11,4673.23 3131.27,4660.07 3202.39,4660.07 3235.24,4692.91 R41.1@3236.22,4692.91
VDD_CORE_1V1: C63.1 C64.1 C65.1 C66.1 C68.1 C69.1 C70.1 C71.1 C72.1 C73.1 C74.1 C75.1 C76.1 C77.1 C78.1 L13.2 L14.2 U9.4 U9.10 U9.18 U9.21 U9.31 U9.36 U9.43 U9.61 U9.63 U9.64 U9.72 U9.80 | length 1092.6
  Top Layer w5.91: L13.2@2303.15,3992.13 2303.15,4090.55 2318.9,4106.3 U9.21@2391.73,4106.3
  Top Layer w7.09: L14.2@2992.13,4263.78 2992.13,4259.84 3000.39,4251.57 3000.59,4251.57 3011.68,4240.49 3057.58,4240.49 3065.45,4232.62 3082.34,4232.62 v1(3082.68,4232.28)
  Top Layer w7.87: U9.43@2842.52,4222.44 2879.46,4222.44 2920.93,4180.98 3019.81,4180.98 3043.31,4157.48 C73.1@3043.31,4153.54 v1(3074.8,4153.54)
  Top Layer w9.84: v1(2228.35,4192.91) C70.1@2228.35,4222.44 U9.18@2314.96,4222.44 ; C69.1@2228.35,4370.08 2235.14,4376.87 2258.86,4376.87 2261.68,4379.69 v1(2265.41,4379.69) 2265.52,4379.81 2314.85,4379.81 U9.10@2314.96,4379.92 ; v1(2229.53,4550.72) 2229.53,4518.9 C68.1@2228.35,4517.72 2253.94,4517.72 2273.62,4498.03 U9.4@2314.96,4498.03 ; C78.1@2342.52,4720.47 v1(2342.52,4688.98) 2345.16,4686.34 2362.87,4686.34 2391.73,4657.48 U9.80@2391.73,4645.67 ; U9.72@2549.21,4633.86 C77.1@2549.21,4720.47 ; U9.63@2726.38,4633.86 U9.63@2727.36,4634.84 ; U9.61@2765.75,4633.86 U9.61@2766.73,4634.84
  other v1: 2228.35,3909.45 2263.78,3940.95 2263.78,3988.19 2645.67,4019.69 2263.78,4035.43 2645.67,4051.18 2716.54,4685.04 2765.75,4685.04 2549.82,4688.27
Vehicle_charge_permission: D23.2 J11.1 R97.2 R98.2 R99.1 | length 2347.4
  Top Layer w7.87: R99.1@3730.31,3020.44 3884.61,3020.44 R97.2@3897.64,3033.46 3897.64,2972.02 3929.13,2940.52 D23.2@3929.13,2914.55 3929.13,2783.46 4035.43,2677.17 4694.88,2677.17 5088.58,3070.87 5088.58,3435.04 J11.1@5216.54,3562.99
XDS_RESET_OUT: D36.1 J24.10 U29.40 | length 955.3
  Top Layer w5.91: J24.10@1563.39,3828.74 1567.21,3824.91 1608.66,3824.91 1658.11,3775.46 1826.65,3775.46 1860.24,3809.06 1860.24,3946.85 1879.92,3966.54 D36.1@1879.92,4007.87 1879.92,4153.54 1781.5,4251.97 1730.9,4251.97 1705.31,4226.38 U29.40@1661.42,4226.38
XDS_RXD: J24.8 U29.33 U30.4 | length 467.2
  Top Layer w5.91: J24.8@1463.39,3828.74 1581.5,3946.85 1673.23,3946.85 1697.83,3971.46 U30.4@1697.83,3994.09 1697.83,4103.35 1685.04,4116.14 U29.33@1661.42,4116.14
XDS_TCK_SWDCLK: J24.14 U29.35 U30.1 | length 450.4
  Top Layer w5.91: U29.35@1661.42,4147.64 1728.35,4147.64 1751.89,4124.09 1751.89,3948.51 1777.9,3922.5 1802.89,3922.5 U30.1@1806.1,3919.29 1806.1,3871.46 J24.14@1763.39,3828.74
XDS_TMS_SWDIO: J24.12 U29.36 U30.3 | length 678
  Top Layer w5.91: U29.36@1661.42,4163.39 1751.97,4163.39 1806.1,4109.25 U30.3@1806.1,3994.09 1813.98,3994.09 1840.55,3967.52 1840.55,3828.74 1799.15,3787.34 1704.79,3787.34 J24.12@1663.39,3828.74
XDS_TXD: J24.6 U29.34 U30.5 | length 736.6
  Top Layer w5.91: J24.6@1363.39,3828.74 1410.11,3782.02 1485.45,3782.02 1515.75,3812.31 1515.75,3858.27 1576.77,3919.29 U30.5@1697.83,3919.29 1698.14,3919.6 1724.72,3919.6 1734.57,3929.45 1734.57,4102.04 1704.72,4131.89 U29.34@1661.42,4131.89
XDS_USB_N: J25.A7 J25.B7 U29.93 U32.3 | length 963.7
  Top Layer w5.91: U29.93@1161.42,4663.39 1161.42,4687.54 1160.43,4688.52 1160.43,4705.51 1131.69,4734.25 1005.8,4734.25 991.52,4734.25 983.75,4742.02 983.75,4753.01 993.19,4762.46 993.19,4773.45 985.86,4780.78 974.87,4780.78 964.65,4770.55 953.66,4770.55 920.28,4803.93 920,4804.21 920,4845.82 944.09,4869.91 944.09,4940.16 974.41,4970.47 1180.9,4970.47 1208.51,4998.08 1208.51,5042.09 1199.02,5051.59 1199.02,5060.8 ; J25.A7@1201.97,5091.54 1199.02,5088.58 1199.02,5068.39 1199.02,5060.8 ; J25.B7@1241.34,5091.54 1238.39,5088.58 1238.39,5068.78 1230.41,5060.8 1199.02,5060.8
XDS_USB_P: J25.A6 J25.B6 U29.94 U32.5 | length 961.1
  Top Layer w5.91: U32.5@896.06,4832.68 905.63,4832.68 906.12,4832.68 906.22,4832.77 906.22,4798.5 984.25,4720.47 1125.98,4720.47 1146.65,4699.8 1146.65,4689.38 1146.05,4688.78 1146.05,4663.76 U29.94@1145.67,4663.39 ; U32.5@905.63,4835.63 905.63,4852.48 930.32,4877.17 930.32,4945.87 968.7,4984.25 1175.2,4984.25 1194.73,5003.79 1194.73,5036.39 1185.24,5045.88 1185.24,5068.39 1185.24,5088.58 J25.B6@1182.28,5091.54 1185.24,5094.49 1185.24,5118.31 1192.91,5125.98 1212.6,5125.98 1220.47,5118.11 1220.47,5092.72 J25.A6@1221.65,5091.54
XDS_VBUS: J25.A4-B9 J25.B4-A9 R158.1 U32.1 | length 1561.9
  Top Layer w7.87: U32.1@954.33,4832.68 974.41,4832.68 984.25,4842.52 984.25,4909.45 1019.68,4944.88 1267.72,4944.88 1307.15,4984.31 J25.A4-B9@1307.15,5085.1
  Top Layer w9.84: R158.1@937.01,4622.05 913.39,4622.05 846.46,4688.98 846.46,4948.82 921.26,5023.62 1090.55,5023.62 1117.32,5050.39 J25.B4-A9@1117.32,5091.54 1117.32,5129.13 1129.92,5141.73 1292.72,5141.73 1305.96,5128.49 1305.96,5091.87 J25.A4-B9@1306.3,5091.54
pads on no net: FID1.1 FID2.1 FID3.1 FID4.1 FID5.1 FID6.1 J25.A8 J25.B8 J27.1 J27.2 J27.3 J27.4 J27.5 J27.7 J28.1 J28.5 J28.6 J28.12 MH1.1 MH2.1 MH3.1 MH4.1 MH5.1 Q1.1@936.02,1958.66 Q1.2@915.35,1958.66 Q1.3@894.68,1958.66 Q2.1@926.18,1033.46 Q2.2@905.51,1033.46 Q2.3@884.84,1033.46 Q3.1@1772.64,2913.39 Q3.2@1751.97,2913.39 Q3.3@1731.3,2913.39 Q4.1@1555.12,3158.46 Q4.2@1555.12,3179.13 Q4.3@1555.12,3199.8 Q5.1@4027.56,4374.02 Q5.2@4027.56,4394.69 Q5.3@4027.56,4415.35 Q6.1@4185.04,4308.07 Q6.2@4185.04,4287.4 Q6.3@4185.04,4266.73 Q7.1@4027.56,4265.75 Q7.2@4027.56,4286.42 Q7.3@4027.56,4307.09 Q8.1@4050.42,3729.33 Q8.2@4050.42,3750 Q8.3@4050.42,3770.67 Q9.1@3944.88,3729.33 Q9.2@3944.88,3750 Q9.3@3944.88,3770.67 Q10.1@3651.57,3630.91 Q10.2@3651.57,3651.57 Q10.3@3651.57,3672.24 Q11.1@3602.36,3630.91 Q11.2@3602.36,3651.57 Q11.3@3602.36,3672.24 Q12.1@4262.8,2901.57 Q12.2@4283.46,2901.57 Q12.3@4304.13,2901.57 Q13.0 Q14.1@3778.54,3176.68 Q14.2@3799.21,3176.68 Q14.3@3819.88,3176.68 Q15.1@4021.85,2104.11 Q15.2@4021.85,2124.78 Q15.3@4021.85,2145.45 Q16.1@4173.23,2353.35 Q16.2@4173.23,2332.68 Q16.3@4173.23,2312.01 SH-J1.0 SH-J2.0 SH-J3.0 SH-J4.0 SH-J5.0 SH-J6.0 SH-J7.0 SH-J8.0 SH-J9.0 SH-J10.0 SH-J11.0 SH-J12.0 SW1.1 SW1.2 SW1.3 SW2.1 SW2.2 SW2.3 SW3.3 SW3.7 T1.2 T1.5 T2.1 T2.4 T2.5 T2.8 U1.3 U2.9 U5.7 U5.12 U5.20 U5.25@1825.04,1845.07 U5.25@1825.04,1895.47 U5.25@1875.44,1845.07 U5.25@1875.44,1895.47 U7.2 U7.7 U7.36 U7.37 U7.50 U7.51 U7.53 U7.58 U7.59 U7.61 U7.63 U7.64 U9.1 U9.2 U9.3 U9.6 U9.7 U9.9 U9.12 U9.13 U9.14 U9.16 U9.17 U9.19 U9.20 U9.22 U9.65 U9.66 U9.68 U14.4 U14.9 U14.11 U25.1 U27.1 U29.1 U29.2 U29.5 U29.6 U29.11 U29.12 U29.13 U29.14 U29.15 U29.18 U29.19 U29.20 U29.21 U29.22 U29.23 U29.24 U29.25 U29.27 U29.29 U29.30 U29.31 U29.32 U29.37 U29.38 U29.41 U29.42 U29.43 U29.44 U29.45 U29.46 U29.49 U29.50 U29.53 U29.54 U29.56 U29.57 U29.65 U29.67 U29.71 U29.72 U29.73 U29.74 U29.75 U29.76 U29.77 U29.78 U29.81 U29.82 U29.83 U29.84 U29.85 U29.86 U29.91 U29.92 U29.95 U29.97 U29.98 U29.99 U29.100 U29.102 U29.103 U29.104 U29.105 U29.106 U29.107 U29.108 U29.109 U29.110 U29.111 U29.112 U29.116 U29.117 U29.118 U29.119 U29.120 U29.121 U29.123 U29.124 U29.125 U29.126 U29.127 U29.128 U32.2 U33.2 U34.2
copper on no net:
  other v1: 915.35,467.52 895.67,492.13 935.04,492.13 915.35,516.73

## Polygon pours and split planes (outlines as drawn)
+12Va on Top Layer "TOP_LAYER_+12VA_P008" (solid, remove dead copper, pour order 8): 2076.77,856.3 2076.77,748.03 2076.77,688.98 2066.93,679.13 2007.87,679.13 1998.03,688.98 1998.03,748.03 1998.03,846.46 1998.03,856.3
-12Va on Top Layer "TOP_LAYER_-12VA_P009" (solid, remove dead copper, pour order 9): 1535.43,866.14 1535.43,649.61 1545.28,639.76 1594.49,639.76 1604.33,649.61 1604.33,846.46 1624.02,866.14
GND on Top Layer "TOP_LAYER_GND_P104" (solid, remove dead copper, pour order 104): 5359.64,5364.98 5361.42,5363.2 5361.42,9.84 610.24,9.84 610.24,3083.46 7.09,3083.46 7.09,5364.17 5361.42,5364.17
PD_VREF on Top Layer "TOP_LAYER_PD_VREF_P012" (solid, remove dead copper, pour order 12): 3330.71,3133.86 3330.71,3051.18 3437.01,3051.18 3444.88,3059.06 3444.88,3102.36 3425.2,3122.05 3393.7,3122.05 3381.89,3133.86
VCCA_3V3 on Top Layer "Top Layer-VCCA_3V3" (solid, remove dead copper, pour order 19): 2980.32,4381.89 3161.42,4381.89 3161.42,4393.7 3259.84,4393.7 3263.78,4397.64 3263.78,4771.65 3259.84,4775.59 3212.6,4775.59 3208.66,4771.65 3208.66,4681.1 3192.91,4665.35 3149.61,4665.35 3141.73,4657.48 3141.73,4480.31 3133.86,4472.44 3055.12,4472.44 3000,4417.32 2980.32,4417.32
NetC21_2 on Top Layer "Top Layer-NetC21_2" (solid, remove dead copper, pour order 20): 1988.19,1259.84 2228.35,1259.84 2255.91,1287.4 2255.91,1898.66 2184.89,1969.68 1997.88,1969.68 1938.82,1910.62 1909.3,1910.62 1909.3,1890.94 2125.98,1890.94 2125.98,1791.34 2137.8,1779.53 2165.35,1779.53 2184.89,1760 2184.89,1358.11 2155.51,1328.74 1988.19,1328.74
NetC30_1 on Top Layer "Top Layer-NetC30_1" (solid, remove dead copper, pour order 13): 1555.12,1259.84 1653.54,1259.84 1653.54,1393.7 1681.1,1421.26 1968.5,1421.26 2047.24,1500 2047.24,1650.63 2035.28,1662.59 1972.29,1662.59 1850.24,1784.64 1850.24,1812.2 1830.56,1812.2 1830.56,1682.28 1901.42,1611.41 1901.42,1536.61 1860.88,1496.06 1618.11,1496.06 1555.12,1433.07
NetC14_2 on Top Layer "Top Layer-NetC14_2" (solid, remove dead copper, pour order 23): 1082.68,1068.9 1117.13,1034.45 1117.13,1000 1149.61,967.52 1149.61,964.57 1230.32,964.57 1230.31,1062.99 1230.32,1161.42 1092.52,1299.21 1043.31,1299.21 1043.31,1279.53 1072.83,1279.53 1082.68,1230.32 1082.68,1102.36
NetC4_2 on Top Layer "Top Layer-NetC4_2" (solid, remove dead copper, pour order 21): 935.04,580.71 954.72,561.02 954.72,118.11 974.41,98.43 1131.89,98.43 1151.57,118.11 1151.57,610.24 1108.27,653.54 1059.06,653.54 1051.18,661.42 1051.18,753.91 1031.5,753.91 1031.5,657.48 1023.62,649.61 980.32,649.61 980.32,717.52 975.39,722.44 944.88,722.44 942.91,720.47 942.91,649.61 942.87,649.61 942.87,639.7 941.98,636.86 935.04,629.92
NetC50_1 on Top Layer "TOP_LAYER_NETC50_1_P033" (solid, remove dead copper, pour order 33): 3271.65,4893.7 3307.09,4929.13 3307.09,4968.5 3299.21,4976.38 3196.85,4976.38 3188.98,4968.5 3188.98,4917.32 3212.6,4893.7
ChargeSeq1 on Top Layer "TOP_LAYER_CHARGESEQ1_P032" (solid, remove dead copper, pour order 32): 4406.5,3027.56 4406.5,3141.73 4619.09,3141.73 4822.83,3345.47 4822.83,3582.68 5117.62,3877.46 5256.4,3877.46 5265.75,3868.11 5265.75,3799.21 5246.06,3779.53 5158.47,3779.53 4921.26,3542.32 4921.26,3287.4 4661.42,3027.56
ChargeSeq2 on Top Layer "TOP_LAYER_CHARGESEQ2_P028" (solid, remove dead copper, pour order 28): 4507.87,2751.97 4507.87,2866.14 4687.01,2866.14 4950.79,3129.92 4950.79,3533.46 5157.48,3740.16 5255.91,3740.16 5267.72,3728.35 5267.72,3653.54 5259.84,3645.67 5200.79,3645.67 5049.21,3494.09 5049.21,3080.71 4720.47,2751.97
12V on Top Layer "TOP_LAYER_12V_P025" (solid, remove dead copper, pour order 25): 4291.34,3070.87 4314.96,3094.49 4314.96,3102.36 4314.96,3210.63 4305.12,3220.47 4196.85,3220.47 4185.04,3208.66 4185.04,3043.31 4196.85,3031.5 4291.34,3031.5
5V on Top Layer "TOP_LAYER_5V_P035" (solid, remove dead copper, pour order 35): 1519.68,2243.11 1480.32,2243.11 1460.63,2223.43 1460.63,2154.53 1480.32,2134.84 1618.11,2134.84 1627.95,2144.68 1627.95,2233.27 1618.11,2243.11
NetC121_2 on Top Layer "TOP_LAYER_NETC121_2_P086" (solid, remove dead copper, pour order 86): 4350.39,1870.08 4537.4,1870.08 4537.4,2185.04 4507.87,2214.57 4478.35,2214.57 4478.35,2175.2 4458.66,2155.51 4458.66,1988.19 4419.29,1948.82 4360.24,1948.82 4350.39,1938.98
NetC50_1 on Top Layer "TOP_LAYER_NETC50_1_P034" (solid, remove dead copper, pour order 34): 3192.91,4669.29 3204.72,4681.1 3204.72,4771.65 3173.23,4803.15 3106.3,4803.15 3106.3,4834.65 3102.36,4838.58 3039.37,4838.58 3035.43,4834.65 3035.43,4791.34 3047.24,4779.53 3072.33,4779.53 3077.84,4774.01 3077.84,4705.62 3094.49,4688.98 3125.98,4688.98 3145.67,4669.29
+12V_EXT on Top Layer "TOP_LAYER_+12V_EXT_P102" (solid, remove dead copper, pour order 102): 3218.5,5127.95 3208.66,5118.11 3120.08,5118.11 3110.24,5127.95 3110.24,5285.43 3120.08,5295.28 3326.77,5295.28 3336.61,5285.43 3336.61,5216.54 3326.77,5206.69 3238.19,5206.69 3228.35,5196.85 3218.5,5187.01
12V on Top Layer "TOP_LAYER_12V_P099" (solid, remove dead copper, pour order 99): 3612.2,5177.17 3622.05,5167.32 3622.05,5049.21 3612.2,5039.37 3395.67,5039.37 3326.77,5108.27 3248.03,5108.27 3238.19,5118.11 3238.19,5167.32 3248.03,5177.17
12V on Top Layer "TOP_LAYER_12V_P016" (solid, remove dead copper, pour order 16): 1135.28,1876.34 1136.18,1876.34 1145.67,1885.83 1145.67,1994.09 1135.83,2003.94 1027.56,2003.94 1017.72,1994.09 1017.72,1885.83 1027.56,1875.98 1135.83,1875.98
3.3V on Top Layer "TOP_LAYER_3.3V_P010" (solid, remove dead copper, pour order 10): 2125.98,3007.87 2145.67,3007.87 2145.67,3066.93 2204.72,3125.98 2318.9,3125.98 2350.39,3157.48 2350.39,3208.66 2346.46,3212.6 2220.47,3212.6 2211.37,3203.49 2211.37,3168.24 2207.39,3164.26 2191.82,3164.26 2125.98,3098.43 2125.98,3066.93
NetC45_2 on Top Layer "TOP_LAYER_NETC45_2_P014" (solid, remove dead copper, pour order 14): 2318.9,2814.96 2318.9,2795.28 2519.69,2795.28 2669.29,2795.28 2669.29,2830.71 2665.35,2834.65 2393.7,2834.65 2385.83,2826.77 2385.83,2818.9 2381.89,2814.96
PL_OUT1 on Top Layer "TOP_LAYER_PL_OUT1_P094" (solid, remove dead copper, pour order 94): 4484.25,2232.28 4484.25,2220.47 4503.94,2220.47 4515.75,2208.66 4551.31,2208.66 4551.31,2230.25 4549.27,2232.28
PL_OUT2 on Top Layer "TOP_LAYER_PL_OUT2_P090" (solid, remove dead copper, pour order 90): 4492.13,2251.97 4490.55,2251.97 4484.25,2251.97 4484.25,2240.16 4486.13,2238.27 4559.06,2238.27 4559.06,2261.79 4521.63,2261.79 4511.81,2251.97 4488.19,2251.97
12V on Top Layer "TOP_LAYER_12V_P089" (solid, remove dead copper, pour order 89): 4350.39,2047.24 4340.55,2037.4 4222.44,2037.4 4192.91,2007.87 4192.91,1879.92 4202.76,1870.08 4330.71,1870.08 4330.71,1948.82 4350.39,1968.5 4409.45,1968.5 4429.13,1988.19 4429.13,2047.24
3.3V on Top Layer "TOP_LAYER_3.3V_P088" (solid, remove dead copper, pour order 88): 3086.61,4389.76 3086.61,4330.71 3181.1,4330.71 3181.1,4389.76
VDD_CORE_1V1 on Top Layer "TOP_LAYER_VDD_CORE_1V1_P037" (solid, remove dead copper, pour order 37): 2212.6,4051.18 2360.24,4051.18 2360.24,3844.49 2212.6,3844.49
NetC55_1 on Top Layer "TOP_LAYER_NETC55_1_P044" (solid, remove dead copper, pour order 44): 2921.26,4468.5 2931.1,4478.35 2966.54,4478.35 3011.81,4478.35 3051.18,4517.72 3120.08,4517.72 3120.08,4581.56 2965.41,4581.56 2891.73,4507.87 2811.02,4507.87 2811.02,4488.19 2874.02,4488.19 2874.02,4429.13 2811.02,4429.13 2811.02,4389.76 2874.02,4389.76 2874.02,4370.08 2811.02,4370.08 2811.02,4350.39 2923.23,4350.39 2921.26,4352.36
NetC60_1 on Top Layer "TOP_LAYER_NETC60_1_P047" (solid, remove dead copper, pour order 47): 2519.68,4137.8 2519.68,4063.66 2503.27,4047.24 2503.27,4007.06 2515.25,3995.08 2515.25,3811.02 2456.69,3811.02 2456.69,3874.02 2460.63,3877.95 2460.63,4137.8
NetL13_1 on Top Layer "TOP_LAYER_NETL13_1_P048" (solid, remove dead copper, pour order 48): 2456.69,3937.01 2456.72,3937.03 2456.72,4137.79 2421.26,4137.79 2421.26,4137.8 2421.26,4074.8 2393.7,4047.24 2393.7,3937.01
VDD_CORE_1V1 on Top Layer "TOP_LAYER_VDD_CORE_1V1_P050" (solid, remove dead copper, pour order 50): 2696.85,4602.36 2696.85,4669.29 2681.1,4685.04 2681.1,4740.16 2811.02,4740.16 2811.02,4696.85 2775.59,4661.42 2775.59,4602.36
VDD_CORE_1V1 on Top Layer "TOP_LAYER_VDD_CORE_1V1_P051" (solid, remove dead copper, pour order 51): 2578.74,4007.87 2578.74,4137.8 2602.36,4137.8 2602.36,4074.8 2673.23,4074.8 2673.23,4137.8 2700.79,4137.8 2700.79,4007.87
Ref_14.5mV on Top Layer "TOP_LAYER_REF_14.5MV_P087" (solid, remove dead copper, pour order 87): 3996.06,2431.1 3946.85,2431.1 3927.17,2411.42 3848.43,2411.42 3838.58,2401.57 3838.58,2381.89 3848.43,2372.05 3887.8,2372.05 3897.64,2362.2 3897.64,2322.83 3907.48,2312.99 3927.17,2312.99 3946.85,2332.68 3946.85,2372.05 3956.69,2381.89 3986.22,2381.89 3996.06,2391.73
NetC137_1 on Top Layer "TOP_LAYER_NETC137_1_P085" (solid, remove dead copper, pour order 85): 2903.54,964.57 2903.54,915.36 2933.07,885.83 2952.75,885.83 2972.44,866.14 3011.81,866.14 3031.49,885.83 3051.18,885.83 3080.7,915.36 3080.7,964.57
NetC142_1 on Top Layer "TOP_LAYER_NETC142_1_P083" (solid, remove dead copper, pour order 83): 2529.53,954.72 2529.53,905.51 2559.06,875.98 2578.74,875.98 2598.43,856.3 2637.8,856.3 2657.48,875.98 2677.17,875.98 2706.69,905.51 2706.69,954.72
+12Va on Top Layer "TOP_LAYER_+12VA_P080" (solid, remove dead copper, pour order 80): 1840.55,1013.78 1840.55,974.41 1870.08,944.88 1870.08,856.3 1879.92,846.46 2066.93,846.46 2076.77,856.3 2076.77,1019.9 2058.8,1037.88 1904.02,1037.88 1879.92,1013.78
-12Va on Top Layer "TOP_LAYER_-12VA_P079" (solid, remove dead copper, pour order 79): 1781.5,1013.78 1781.5,974.41 1751.97,944.88 1751.97,866.14 1742.13,856.3 1535.43,856.3 1535.43,1023.62 1550.07,1038.26 1715.24,1038.26 1751.97,1013.78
